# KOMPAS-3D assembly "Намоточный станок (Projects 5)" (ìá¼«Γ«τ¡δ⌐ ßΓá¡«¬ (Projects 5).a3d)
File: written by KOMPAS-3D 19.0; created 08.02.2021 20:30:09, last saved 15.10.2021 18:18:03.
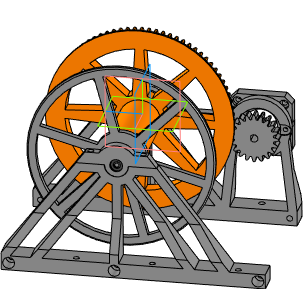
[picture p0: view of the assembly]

Document properties: Автор: Agent Smith; Полное имя файла: D:\3D_print\3D проекты Компас 3D\Халява Projects 5\Намоточный станок (Projects 5).a3d

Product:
- Part/product: Намоточный станок (Projects 5)
    Материал: АБС 0603Т ТУ 2214-019-002 03521-96 (density 0 kg/m3)
    Масса: 1.16567
  - Component [detail]: Переходник на Nema_17  | Масса: 0.0762675; source file: Переходник на Nema_17.m3d
  - Component [detail]: 28BYJ-48_Motor  | Масса: 0.100949; source file: 28BYJ-48_Motor.m3d
  - Component [detail]: Рама_основная  | Масса: 0.415808; source file: Рама_основная.m3d
  - Component [detail]: Vedom_koleso  | Материал: Полиэтилен 20108-001 ГОСТ 16338-85 (density 949 kg/m3); Масса: 0.0863366; source file: ..\Халява Projects\Vedom_koleso.m3d
  - Component [detail]: Vedom_Krugl  | Материал: Полиэтилен 20108-001 ГОСТ 16338-85 (density 949 kg/m3); Масса: 0.0174592; source file: ..\Халява Projects\Vedom_Krugl.m3d
  - Component [detail]: Втулка_намоточного  | qty 2  | Материал: Полиэтилен 20108-001 ГОСТ 16338-85 (density 949 kg/m3); Масса: 0.00235951; source file: Втулка_намоточного.m3d
  - Component [detail]: Подшипник  | qty 2  | Материал: Сталь ШХ-10 ГОСТ 808-70 (density 7850 kg/m3); Масса: 0.00697738; source file: ..\Халява Projects_3\Подшипник.m3d
  - Component [detail]: Крышка_подшипника  | qty 2  | Масса: 0.0173967; source file: Крышка_подшипника.m3d
  - Component [detail]: Рама_вспомогательная  | Масса: 0.367054; source file: Рама_вспомогательная .m3d
  - Component [detail]: Ведущая_шестреня  | Материал: АБС 0603Т ТУ 2214-019-002 03521-96 (density 0 kg/m3); source file: Ведущая_шестреня .m3d
  - Component [detail]: Ведущая щестерня под ne17  | Масса: 0.0483297; source file: Ведущая щестерня под ne17.m3d

Referenced files in D:\3D_print\3D проекты Компас 3D\Халява Projects\: Vedom_koleso.m3d, Vedom_Krugl.m3d
Referenced files in D:\3D_print\3D проекты Компас 3D\Халява Projects 5\: Втулка_намоточного.m3d, Рама_основная.m3d, 28BYJ-48_Motor.m3d, Крышка_подшипника.m3d, Рама_вспомогательная .m3d, Ведущая_шестреня .m3d, Переходник на Nema_17.m3d, Ведущая щестерня под ne17.m3d
Referenced files in D:\3D_print\3D проекты Компас 3D\Халява Projects_3\: Подшипник.m3d
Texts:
  Втулка_намоточного (1)
  Втулка_намоточного (2)
  Подшипник (1)
  Подшипник (2)
  Крышка_подшипника (1)
  Крышка_подшипника (2)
